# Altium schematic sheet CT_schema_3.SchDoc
size 576 x 267 mm
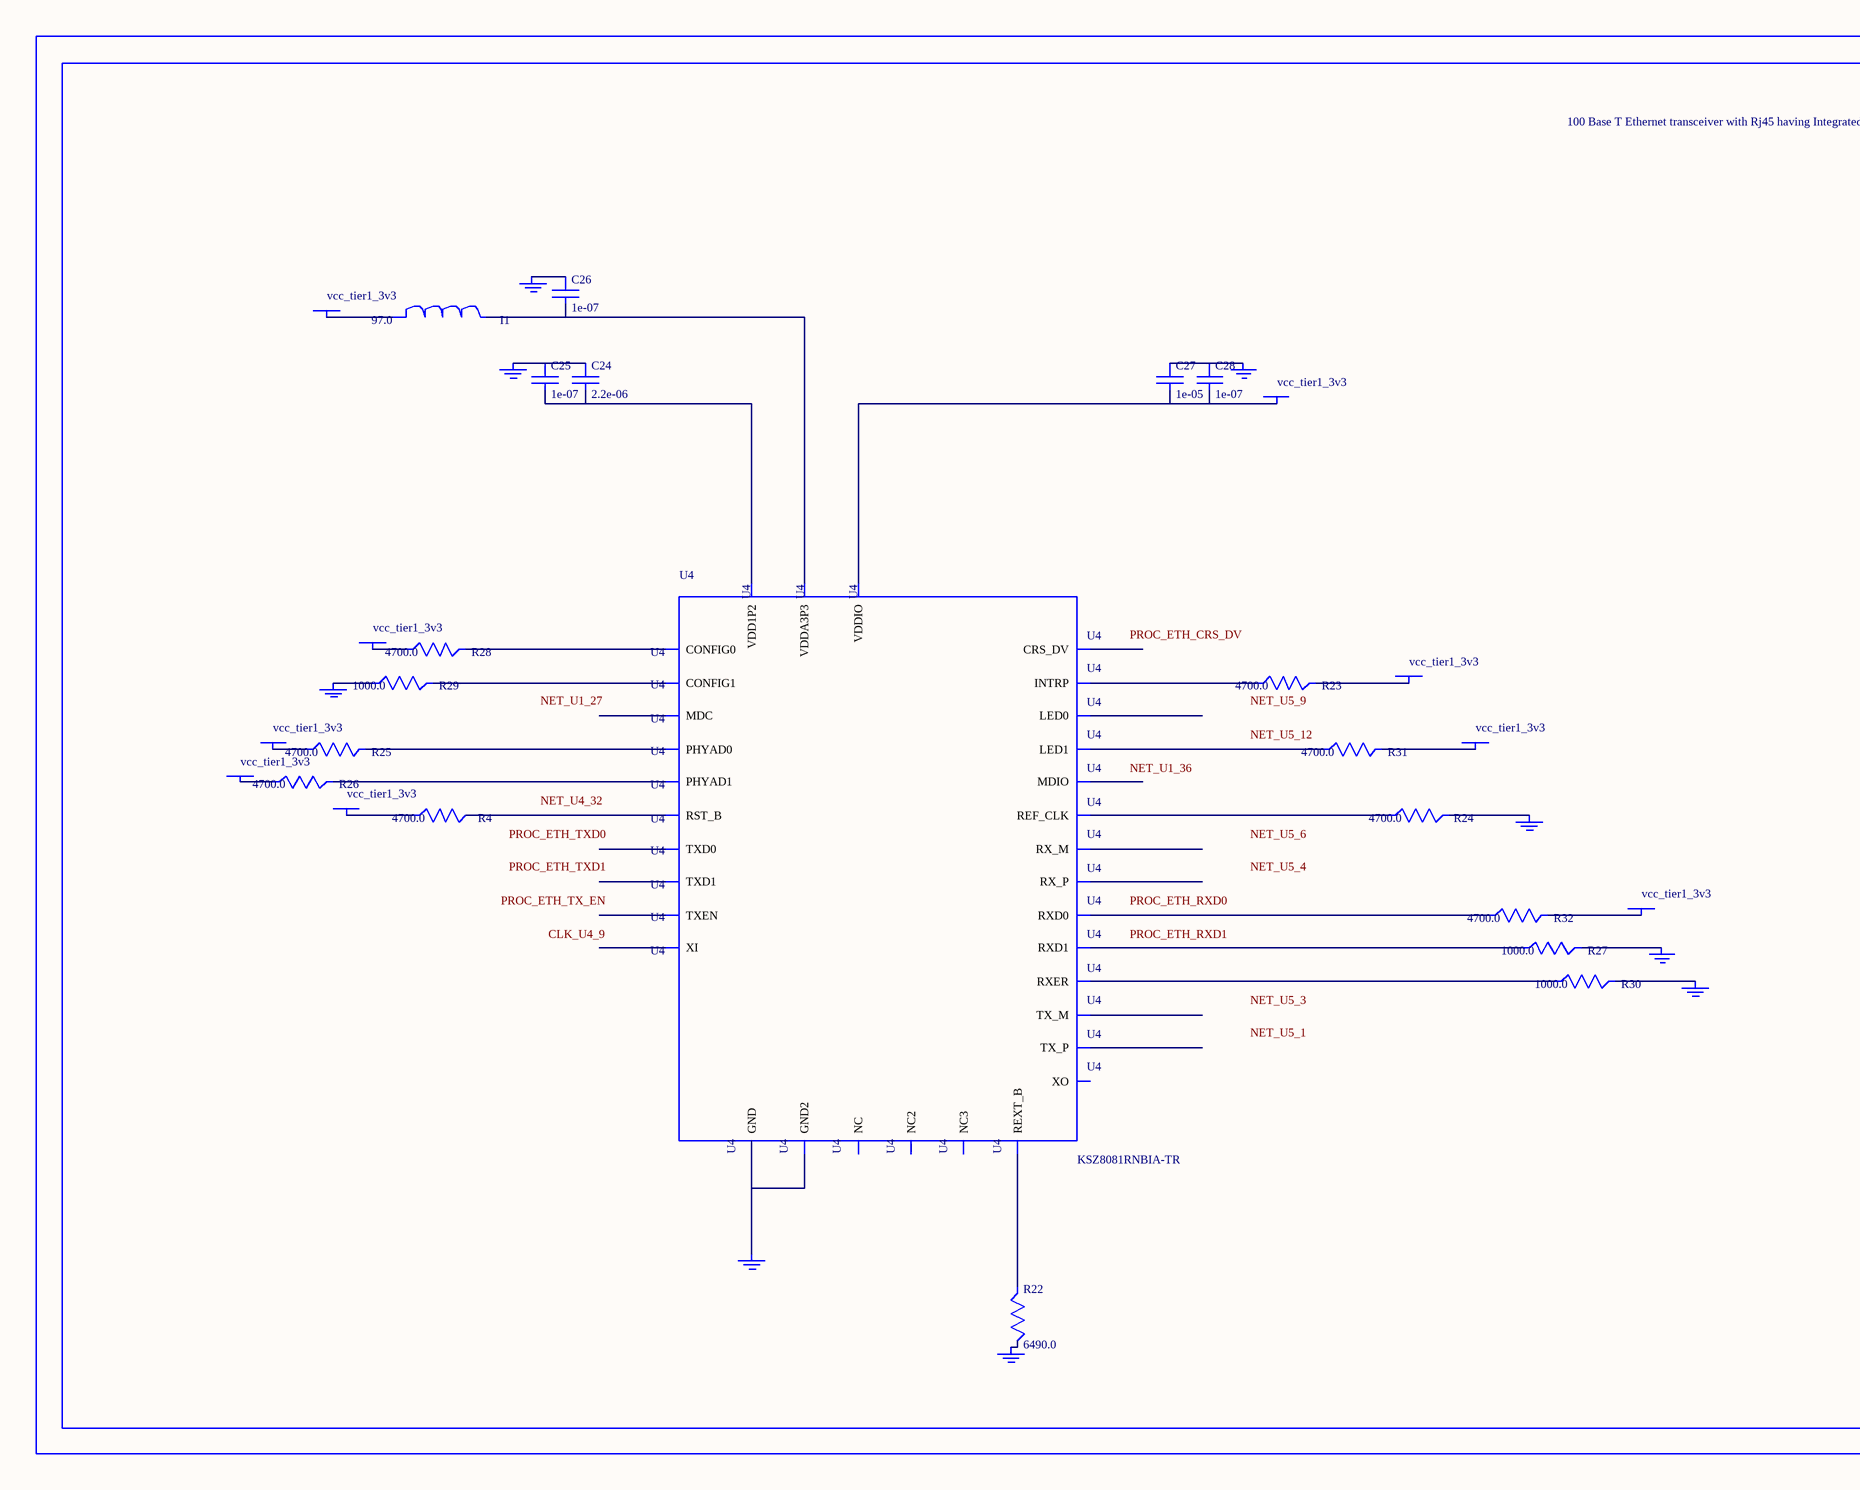
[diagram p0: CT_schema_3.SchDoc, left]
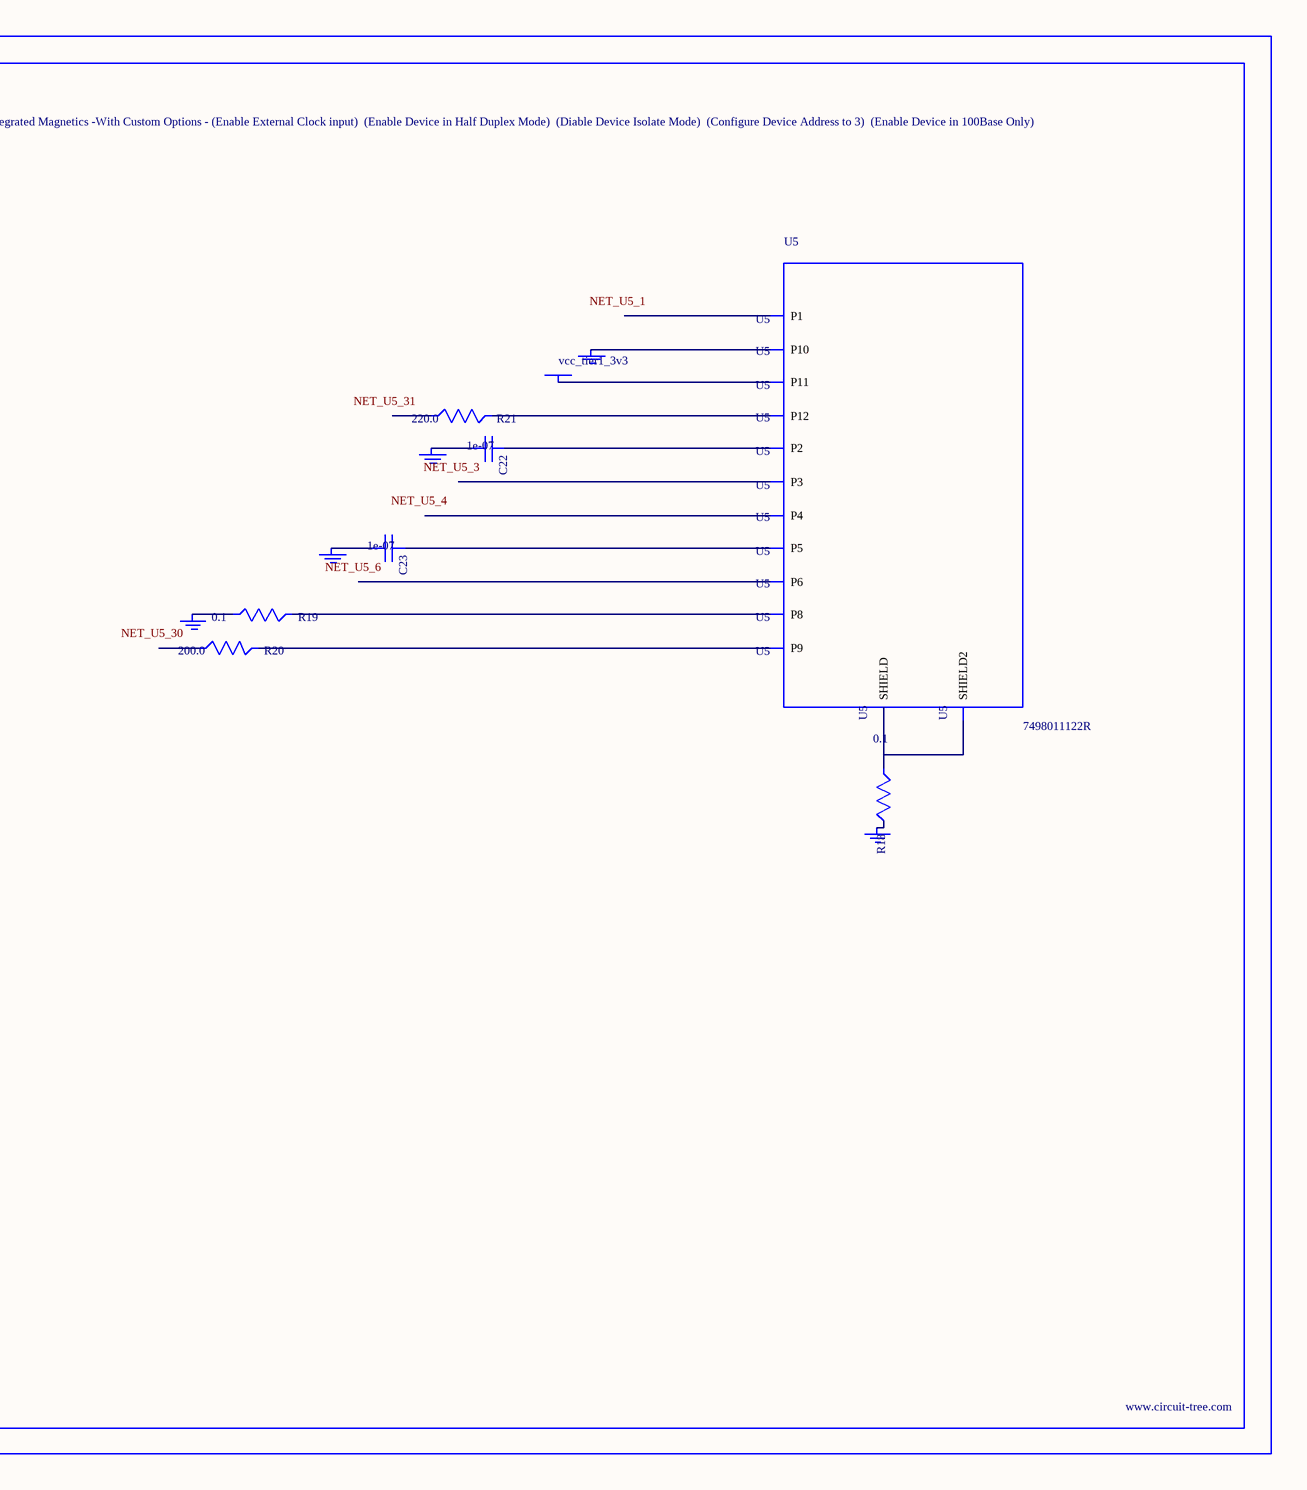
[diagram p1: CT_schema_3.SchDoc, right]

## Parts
BORDER2  (no value)
C22  1e-07  [C0402]
C23  1e-07  [C0402]
C24  2.2e-06  [C0603]
C25  1e-07  [C0402]
C26  1e-07  [C0402]
C27  1e-05  [C0805]
C28  1e-07  [C0402]
GND_INSTANCE_2_0  (no value)
GND_INSTANCE_2_1  (no value)
GND_INSTANCE_2_2  (no value)
GND_INSTANCE_2_3  (no value)
GND_INSTANCE_2_4  (no value)
GND_INSTANCE_2_5  (no value)
GND_INSTANCE_2_6  (no value)
GND_INSTANCE_2_7  (no value)
GND_INSTANCE_2_8  (no value)
GND_INSTANCE_2_9  (no value)
GND_INSTANCE_2_10  (no value)
GND_INSTANCE_2_11  (no value)
GND_INSTANCE_2_12  (no value)
GND_INSTANCE_2_13  (no value)
I1  97.0  [R0603]
POWER_INSTANCE_2_0  vcc_tier1_3v3
POWER_INSTANCE_2_1  vcc_tier1_3v3
POWER_INSTANCE_2_2  vcc_tier1_3v3
POWER_INSTANCE_2_3  vcc_tier1_3v3
POWER_INSTANCE_2_4  vcc_tier1_3v3
POWER_INSTANCE_2_5  vcc_tier1_3v3
POWER_INSTANCE_2_6  vcc_tier1_3v3
POWER_INSTANCE_2_7  vcc_tier1_3v3
POWER_INSTANCE_2_8  vcc_tier1_3v3
POWER_INSTANCE_2_9  vcc_tier1_3v3
R4  4700.0  [R0603]
R18  0.1  [R0603]
R19  0.1  [R0603]
R20  200.0  [R0603]
R21  220.0  [R0603]
R22  6490.0  [R0603]
R23  4700.0  [R0603]
R24  4700.0  [R0603]
R25  4700.0  [R0603]
R26  4700.0  [R0603]
R27  1000.0  [R0603]
R28  4700.0  [R0603]
R29  1000.0  [R0603]
R30  1000.0  [R0603]
R31  4700.0  [R0603]
R32  4700.0  [R0603]
U4  KSZ8081RNBIA-TR  [QFN-32]
U5  7498011122R  [7498011122R]

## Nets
NetC22_1: C22.1 U5.2(P2)
NetC22_2: C22.2 GND_INSTANCE_2_9.0(GND)
NetC23_1: C23.1 U5.5(P5)
NetC23_2: C23.2 GND_INSTANCE_2_10.0(GND)
NetC24_1: C24.1 C25.1 GND_INSTANCE_2_0.0(GND)
NetC24_2: C24.2 C25.2 U4.2(VDD1P2)
NetC26_1: C26.1 GND_INSTANCE_2_1.0(GND)
NetC26_2: C26.2 I1.2 U4.3(VDDA3P3)
NetC27_1: C27.1 C28.1 GND_INSTANCE_2_4.0(GND)
NetC27_2: C27.2 C28.2 POWER_INSTANCE_2_4.0(PWR) U4.17(VDDIO)
NetGND_INSTANCE_2_2_0: GND_INSTANCE_2_2.0(GND) R22.2
NetGND_INSTANCE_2_3_0: GND_INSTANCE_2_3.0(GND) R27.2
NetGND_INSTANCE_2_5_0: GND_INSTANCE_2_5.0(GND) R24.2
NetGND_INSTANCE_2_6_0: GND_INSTANCE_2_6.0(GND) R30.2
NetGND_INSTANCE_2_7_0: GND_INSTANCE_2_7.0(GND) R29.1
NetGND_INSTANCE_2_8_0: GND_INSTANCE_2_8.0(GND) U4.1(GND) U4.EXP(GND2)
NetGND_INSTANCE_2_11_0: GND_INSTANCE_2_11.0(GND) R19.1
NetGND_INSTANCE_2_12_0: GND_INSTANCE_2_12.0(GND) U5.10(P10)
NetGND_INSTANCE_2_13_0: GND_INSTANCE_2_13.0(GND) R18.2
NetI1_1: I1.1 POWER_INSTANCE_2_0.0(PWR)
NetPOWER_INSTANCE_2_1_0: POWER_INSTANCE_2_1.0(PWR) R25.1
NetPOWER_INSTANCE_2_2_0: POWER_INSTANCE_2_2.0(PWR) R26.1
NetPOWER_INSTANCE_2_3_0: POWER_INSTANCE_2_3.0(PWR) R32.2
NetPOWER_INSTANCE_2_5_0: POWER_INSTANCE_2_5.0(PWR) R23.2
NetPOWER_INSTANCE_2_6_0: POWER_INSTANCE_2_6.0(PWR) R28.1
NetPOWER_INSTANCE_2_7_0: POWER_INSTANCE_2_7.0(PWR) R31.2
NetPOWER_INSTANCE_2_8_0: POWER_INSTANCE_2_8.0(PWR) R4.1
NetPOWER_INSTANCE_2_9_0: POWER_INSTANCE_2_9.0(PWR) U5.11(P11)
NetR4_2: R4.2 U4.32(RST_B)
NetR18_1: R18.1 U5.13(SHIELD) U5.14(SHIELD2)
NetR19_2: R19.2 U5.8(P8)
NetR20_2: R20.2 U5.9(P9)
NetR21_2: R21.2 U5.12(P12)
NetR22_1: R22.1 U4.10(REXT_B)
NetR23_1: R23.1 U4.21(INTRP)
NetR24_1: R24.1 U4.19(REF_CLK)
NetR25_2: R25.2 U4.13(PHYAD0)
NetR26_2: R26.2 U4.14(PHYAD1)
NetR27_1: R27.1 U4.15(RXD1)
NetR28_2: R28.2 U4.28(CONFIG0)
NetR29_2: R29.2 U4.29(CONFIG1)
NetR30_1: R30.1 U4.20(RXER)
NetR31_1: R31.1 U4.31(LED1)
NetR32_1: R32.1 U4.16(RXD0)

Not connected (* = marked no-connect by the designer): R20 1; R21 1; U4 4(RX_M) 5(RX_P) 6(TX_M) 7(TX_P) 8(XO) 9(XI) 11(MDIO) 12(MDC) 18(CRS_DV) 22(NC) 23(TXEN) 24(TXD0) 25(TXD1) 26(NC2) 27(NC3) 30(LED0); U5 1(P1) 3(P3) 4(P4) 6(P6)

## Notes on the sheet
- Labels drawn without touching a wire or pin: CLK_U4_9, NET_U1_27, NET_U1_36, NET_U4_32, NET_U5_1, NET_U5_3, NET_U5_4, NET_U5_6, NET_U5_9, NET_U5_12, NET_U5_30, NET_U5_31, PROC_ETH_CRS_DV, PROC_ETH_RXD0, PROC_ETH_RXD1, PROC_ETH_TX_EN, PROC_ETH_TXD0, PROC_ETH_TXD1

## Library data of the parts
BORDER2 = BORDER_PAGE2
C22 C23 C25 C26 C28 = C0402C104K3RACTU
C24 = C0603C225K8RACTU
C27 = C0805C106K8RACTU
GND_INSTANCE_2_0-GND_INSTANCE_2_13 = GND
I1 = I1
POWER_INSTANCE_2_0-POWER_INSTANCE_2_9 = PWR
R4 R23-R26 R28 R31 R32 = RC0603JR-074K7L
R18 R19 = ERJ-3RSFR10V
R20 = RC0603JR-07200RL
R21 = RC0603JR-07220RL
R22 = ERJ-3EKF6491V
R27 R29 R30 = RC0603JR-071KL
